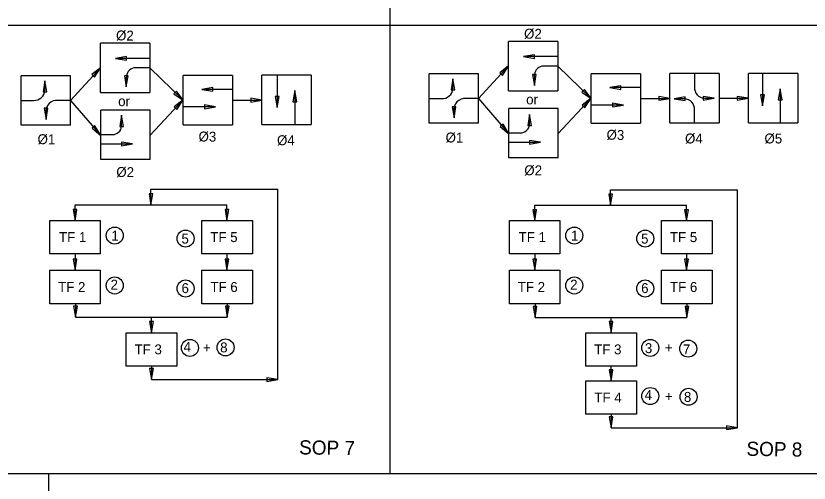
# Model space of a CAD drawing. Extents: x 10027 to 10796, y 10033 to 10528.
# Drawn here: x 10372.3 to 10652, y 10201.9 to 10366.7 of the extents above; entities that cross this region are included whole.
import ezdxf

# ---------------------------------------------------------------- set-up
doc = ezdxf.new("R2010")
doc.units = 0
for name, color, linetype in [('AdhocPoint_dp', 7, 'Continuous'), ('Default', 7, 'Continuous'), ('Dimension', 7, 'Continuous'), ('DSIndex', 7, 'Continuous'), ('PlotBorder_dp', 7, 'Continuous')]:
    doc.layers.add(name, color=color, linetype=linetype)

msp = doc.modelspace()

# ---------------------------------------------------------------- linework, layer by layer
at = {"layer": 'AdhocPoint_dp'}
for p, q in [((10504.32, 10205.22), (10504.32, 10528.43)), ((10027.5, 10363.43), (10662.13, 10363.43)), ((10662.13, 10205.22), (10027.5, 10205.22)), ((10383.78, 10205.22), (10383.78, 10033.43))]:
    msp.add_line(p, q, dxfattribs=at)
at = {"layer": 'Default'}
for p, q in [((10402.15, 10339.66), (10402.15, 10357.05)), ((10419.55, 10357.05), (10402.15, 10357.05)), ((10419.55, 10357.05), (10419.55, 10339.66)), ((10546.04, 10340.27), (10546.04, 10357.66)), ((10563.44, 10357.66), (10546.04, 10357.66)), ((10563.44, 10357.66), (10563.44, 10340.27)), ((10419.55, 10351.72), (10407.36, 10351.72)), ((10563.44, 10352.33), (10551.26, 10352.33)), ((10391.55, 10336.91), (10402.15, 10348.41)), ((10535.45, 10337.52), (10546.04, 10349.03)), ((10563.44, 10348.97), (10557.78, 10348.97)), ((10563.44, 10348.97), (10575.14, 10337.6)), ((10391.55, 10345.6), (10374.16, 10345.6)), ((10374.16, 10328.21), (10374.16, 10345.6)), ((10391.55, 10328.21), (10391.55, 10345.6)), ((10419.55, 10348.35), (10413.89, 10348.35)), ((10419.55, 10348.35), (10431.25, 10336.98)), ((10431.25, 10328.28), (10431.25, 10345.68)), ((10448.65, 10345.68), (10431.25, 10345.68)), ((10448.65, 10345.68), (10448.65, 10328.28)), ((10459.05, 10328.34), (10459.05, 10345.73)), ((10476.44, 10345.73), (10459.05, 10345.73)), ((10464.43, 10345.73), (10464.43, 10334.34)), ((10476.44, 10345.73), (10476.44, 10328.34)), ((10535.45, 10346.22), (10518.05, 10346.22)), ((10518.05, 10328.82), (10518.05, 10346.22)), ((10535.45, 10328.82), (10535.45, 10346.22)), ((10575.14, 10328.9), (10575.14, 10346.29)), ((10592.54, 10346.29), (10575.14, 10346.29)), ((10592.54, 10346.29), (10592.54, 10328.9)), ((10602.94, 10328.95), (10602.94, 10346.35)), ((10620.34, 10346.35), (10602.94, 10346.35)), ((10611.6, 10346.35), (10611.6, 10341.64)), ((10620.34, 10346.35), (10620.34, 10328.95)), ((10630.6, 10328.97), (10630.6, 10346.36)), ((10648, 10346.36), (10630.6, 10346.36)), ((10635.59, 10346.36), (10635.59, 10334.97)), ((10648, 10346.36), (10648, 10328.97)), ((10382.51, 10340.42), (10382.51, 10340.84)), ((10448.65, 10340.79), (10437.86, 10340.79)), ((10470.66, 10340.34), (10470.66, 10328.34)), ((10526.41, 10341.03), (10526.41, 10341.46)), ((10546.04, 10340.27), (10563.44, 10340.27)), ((10592.54, 10341.4), (10581.75, 10341.4)), ((10641.82, 10340.97), (10641.82, 10328.97)), ((10402.15, 10339.66), (10419.55, 10339.66)), ((10518.05, 10337.52), (10522.39, 10337.52)), ((10535.45, 10337.52), (10531.01, 10337.52)), ((10535.45, 10337.52), (10546.13, 10325.14)), ((10563.52, 10325.24), (10575.14, 10337.66)), ((10592.54, 10337.6), (10602.94, 10337.6)), ((10608.07, 10337.49), (10607.65, 10337.49)), ((10615.11, 10337.63), (10616.06, 10337.63)), ((10620.34, 10337.65), (10630.6, 10337.65)), ((10374.16, 10336.91), (10378.5, 10336.91)), ((10391.55, 10336.91), (10387.17, 10336.91)), ((10391.55, 10336.91), (10402.23, 10324.53)), ((10419.7, 10324.71), (10431.25, 10337.04)), ((10442.72, 10334.62), (10431.25, 10334.62)), ((10448.65, 10336.98), (10459.05, 10336.98)), ((10586.62, 10335.24), (10575.14, 10335.24)), ((10419.63, 10333.4), (10402.23, 10333.4)), ((10402.23, 10316.01), (10402.23, 10333.4)), ((10419.63, 10316.01), (10419.63, 10333.4)), ((10563.52, 10334.02), (10546.13, 10334.02)), ((10546.13, 10316.62), (10546.13, 10334.02)), ((10563.52, 10316.62), (10563.52, 10334.02)), ((10611.6, 10328.95), (10611.6, 10333.36)), ((10535.45, 10328.82), (10518.05, 10328.82)), ((10575.14, 10328.9), (10592.54, 10328.9)), ((10602.94, 10328.95), (10620.34, 10328.95)), ((10630.6, 10328.97), (10648, 10328.97)), ((10391.55, 10328.21), (10374.16, 10328.21)), ((10431.25, 10328.28), (10448.65, 10328.28)), ((10459.05, 10328.34), (10476.44, 10328.34)), ((10402.23, 10324.89), (10407.02, 10324.89)), ((10546.13, 10325.5), (10550.77, 10325.5)), ((10402.23, 10321.52), (10413.43, 10321.52)), ((10546.13, 10322.14), (10557.32, 10322.14)), ((10419.63, 10316.01), (10402.23, 10316.01)), ((10563.52, 10316.62), (10546.13, 10316.62)), ((10419.92, 10300.06), (10419.92, 10305.56)), ((10419.92, 10305.56), (10464.69, 10305.56)), ((10464.69, 10238.43), (10464.69, 10305.56)), ((10582.01, 10299.91), (10582.01, 10305.4)), ((10582.01, 10305.4), (10626.78, 10305.4)), ((10626.78, 10221.46), (10626.78, 10305.4)), ((10393.15, 10294.57), (10393.15, 10300.06)), ((10393.15, 10300.06), (10446.69, 10300.06)), ((10446.69, 10294.57), (10446.69, 10300.06)), ((10555.24, 10294.41), (10555.24, 10299.91)), ((10555.24, 10299.91), (10608.78, 10299.91)), ((10608.78, 10294.41), (10608.78, 10299.91)), ((10393.15, 10282.81), (10393.15, 10276.98)), ((10446.69, 10282.81), (10446.69, 10276.98)), ((10555.24, 10282.81), (10555.24, 10276.98)), ((10608.78, 10282.81), (10608.78, 10276.98)), ((10393.28, 10265.22), (10393.28, 10260.47)), ((10446.83, 10265.22), (10446.83, 10260.47)), ((10555.37, 10265.07), (10555.37, 10260.32)), ((10608.92, 10265.07), (10608.92, 10260.32)), ((10393.28, 10260.47), (10446.83, 10260.47)), ((10420.11, 10254.97), (10420.11, 10260.47)), ((10555.37, 10260.32), (10608.92, 10260.32)), ((10582.2, 10255.04), (10582.2, 10260.32)), ((10420.11, 10243.22), (10420.11, 10238.43)), ((10582.2, 10238.01), (10582.2, 10243.29)), ((10420.11, 10238.43), (10464.69, 10238.43)), ((10582.2, 10226.25), (10582.2, 10221.46)), ((10582.2, 10221.46), (10626.78, 10221.46))]:
    msp.add_line(p, q, dxfattribs=at)
for centre in [(10433.67, 10249.63), (10446.22, 10249.8)]:
    msp.add_circle(centre, 3, dxfattribs=at)
for centre, radius, start, end in [((10558.55, 10345.62), 3.44, 102.998, 182.423), ((10414.66, 10345), 3.44, 102.998, 182.423), ((10378.74, 10340.68), 3.78, 266.3242, 356.0955), ((10522.64, 10341.29), 3.78, 266.3242, 356.0955), ((10615.37, 10341.4), 3.78, 176.3242, 266.0955), ((10530.63, 10333.66), 3.88, 84.3849, 188.3023), ((10607.82, 10333.72), 3.78, 356.3242, 86.0955), ((10386.75, 10333.05), 3.88, 83.7387, 188.217), ((10550.31, 10328.63), 3.16, 278.4278, 6.6131), ((10406.42, 10328.02), 3.16, 278.4278, 6.6131)]:
    msp.add_arc(centre, radius, start, end, dxfattribs=at)
at = {"layer": 'Dimension'}
for p, q in [((10382.51, 10340.84), (10382.51, 10343.76)), ((10411.22, 10344.86), (10411.22, 10341.71)), ((10526.41, 10341.46), (10526.41, 10344.46)), ((10555.12, 10345.47), (10555.12, 10342.16)), ((10607.65, 10337.49), (10604.42, 10337.49)), ((10616.06, 10337.63), (10616.06, 10337.62)), ((10616.06, 10337.62), (10618.6, 10337.62)), ((10382.91, 10332.49), (10382.91, 10330.21)), ((10409.56, 10328.38), (10409.56, 10331.63)), ((10526.79, 10333.1), (10526.79, 10330.75)), ((10553.45, 10328.99), (10553.45, 10331.92))]:
    msp.add_line(p, q, dxfattribs=at)
for centre in [(10407.13, 10289.22), (10432.13, 10288.16), (10569.22, 10289.22), (10594.22, 10288.16), (10407.13, 10271.63), (10432.13, 10270.57), (10569.22, 10271.63), (10594.22, 10270.57), (10596.02, 10249.63), (10609.39, 10249.36), (10596.01, 10232.66), (10609.51, 10232.41)]:
    msp.add_circle(centre, 3, dxfattribs=at)
at = {"layer": 'DSIndex'}
for points in [[(10384.24, 10294.57), (10402.06, 10294.57), (10402.06, 10282.81), (10384.24, 10282.81)], [(10437.89, 10294.57), (10455.72, 10294.57), (10455.72, 10282.81), (10437.89, 10282.81)], [(10546.33, 10294.57), (10564.15, 10294.57), (10564.15, 10282.81), (10546.33, 10282.81)], [(10599.98, 10294.57), (10617.81, 10294.57), (10617.81, 10282.81), (10599.98, 10282.81)], [(10384.24, 10276.98), (10402.06, 10276.98), (10402.06, 10265.22), (10384.24, 10265.22)], [(10437.89, 10276.98), (10455.72, 10276.98), (10455.72, 10265.22), (10437.89, 10265.22)], [(10546.33, 10276.98), (10564.15, 10276.98), (10564.15, 10265.22), (10546.33, 10265.22)], [(10599.98, 10276.98), (10617.81, 10276.98), (10617.81, 10265.22), (10599.98, 10265.22)], [(10411.2, 10254.97), (10429.02, 10254.97), (10429.02, 10243.22), (10411.2, 10243.22)], [(10573.29, 10254.97), (10591.11, 10254.97), (10591.11, 10243.22), (10573.29, 10243.22)], [(10573.29, 10238.01), (10591.11, 10238.01), (10591.11, 10226.25), (10573.29, 10226.25)]]:
    msp.add_lwpolyline(points, close=True, dxfattribs=at)
at = {"layer": 'PlotBorder_dp'}
for points in [[(10407.36, 10351.72), (10411.27, 10351.06), (10411.27, 10352.38)], [(10551.26, 10352.33), (10555.16, 10351.67), (10555.16, 10352.99)], [(10402.15, 10348.41), (10399.02, 10345.99), (10399.99, 10345.09)], [(10546.04, 10349.03), (10542.91, 10346.6), (10543.89, 10345.71)], [(10411.22, 10341.71), (10411.88, 10345.61), (10410.56, 10345.61)], [(10555.12, 10342.16), (10555.78, 10346.07), (10554.45, 10346.07)], [(10382.51, 10343.76), (10381.85, 10339.86), (10383.17, 10339.86)], [(10526.41, 10344.46), (10525.74, 10340.56), (10527.07, 10340.56)], [(10431.25, 10336.98), (10428.91, 10340.18), (10427.99, 10339.23)], [(10437.86, 10340.79), (10441.76, 10340.13), (10441.76, 10341.45)], [(10470.66, 10340.34), (10470, 10336.44), (10471.32, 10336.44)], [(10575.14, 10337.6), (10572.8, 10340.79), (10571.88, 10339.84)], [(10581.75, 10341.4), (10585.66, 10340.74), (10585.66, 10342.07)], [(10641.82, 10340.97), (10641.16, 10337.07), (10642.48, 10337.07)], [(10459.05, 10336.98), (10455.14, 10337.64), (10455.14, 10336.32)], [(10464.43, 10334.34), (10465.09, 10338.24), (10463.76, 10338.24)], [(10575.14, 10337.66), (10571.99, 10335.26), (10572.96, 10334.35)], [(10602.94, 10337.6), (10599.04, 10338.26), (10599.04, 10336.93)], [(10604.42, 10337.49), (10608.33, 10336.83), (10608.33, 10338.15)], [(10618.6, 10337.62), (10614.69, 10338.28), (10614.69, 10336.96)], [(10630.6, 10337.65), (10626.7, 10338.31), (10626.7, 10336.99)], [(10635.59, 10334.97), (10636.25, 10338.87), (10634.93, 10338.87)], [(10431.25, 10337.04), (10428.1, 10334.64), (10429.06, 10333.74)], [(10442.72, 10334.62), (10438.82, 10335.29), (10438.82, 10333.96)], [(10526.79, 10330.75), (10527.45, 10334.65), (10526.13, 10334.65)], [(10586.62, 10335.24), (10582.71, 10335.9), (10582.71, 10334.58)], [(10382.91, 10330.21), (10383.57, 10334.12), (10382.25, 10334.12)], [(10409.56, 10331.63), (10408.9, 10327.73), (10410.22, 10327.73)], [(10553.45, 10331.92), (10552.79, 10328.01), (10554.11, 10328.01)], [(10402.23, 10324.53), (10400.18, 10327.91), (10399.18, 10327.05)], [(10546.13, 10325.14), (10544.08, 10328.53), (10543.08, 10327.67)], [(10413.43, 10321.52), (10409.52, 10322.18), (10409.52, 10320.86)], [(10557.32, 10322.14), (10553.41, 10322.8), (10553.41, 10321.48)], [(10419.92, 10300.06), (10420.58, 10303.97), (10419.26, 10303.97)], [(10582.01, 10299.91), (10582.67, 10303.81), (10581.35, 10303.81)], [(10393.15, 10294.57), (10393.81, 10298.47), (10392.49, 10298.47)], [(10446.69, 10294.57), (10447.35, 10298.47), (10446.03, 10298.47)], [(10555.24, 10294.41), (10555.9, 10298.32), (10554.58, 10298.32)], [(10608.78, 10294.41), (10609.45, 10298.32), (10608.12, 10298.32)], [(10393.15, 10276.98), (10393.81, 10280.88), (10392.49, 10280.88)], [(10446.69, 10276.98), (10447.35, 10280.88), (10446.03, 10280.88)], [(10555.24, 10276.98), (10555.9, 10280.88), (10554.58, 10280.88)], [(10608.78, 10276.98), (10609.45, 10280.88), (10608.12, 10280.88)], [(10393.28, 10260.47), (10393.95, 10264.38), (10392.62, 10264.38)], [(10446.83, 10260.47), (10447.49, 10264.38), (10446.17, 10264.38)], [(10555.37, 10260.32), (10556.04, 10264.22), (10554.71, 10264.22)], [(10608.92, 10260.32), (10609.58, 10264.22), (10608.26, 10264.22)], [(10420.11, 10254.97), (10420.77, 10258.88), (10419.45, 10258.88)], [(10582.2, 10255.04), (10582.86, 10258.95), (10581.54, 10258.95)], [(10420.11, 10238.43), (10420.77, 10242.34), (10419.45, 10242.34)], [(10582.2, 10238.01), (10582.86, 10241.91), (10581.54, 10241.91)], [(10464.69, 10238.43), (10460.79, 10239.09), (10460.79, 10237.77)], [(10582.2, 10221.46), (10582.86, 10225.37), (10581.54, 10225.37)], [(10582.2, 10221.46), (10582.86, 10225.37), (10581.54, 10225.37)], [(10626.78, 10221.46), (10622.88, 10222.13), (10622.88, 10220.8)]]:
    msp.add_lwpolyline(points, close=True, dxfattribs=at)

# ---------------------------------------------------------------- texts
at = {"layer": 'Default'}
for s, height, rotation, p in [('4', 3.5, 359.6943, (10431.42, 10248.26)), ('8', 3.5, 359.6943, (10444.31, 10248.06)), ('SOP 7', 5, 359.1183, (10472.14, 10212.09)), ('SOP 8', 5, 359.1183, (10629.91, 10211.59))]:
    msp.add_text(s, height=height, rotation=rotation, dxfattribs=at).set_placement(p)
msp.add_text('+', height=3.5, dxfattribs=at).set_placement((10438.29, 10248))
at = {"layer": 'Dimension'}
for s, rotation, p in [('Ø2', 359.1183, (10407.58, 10358.07)), ('Ø2', 359.1183, (10551.48, 10358.69)), ('or', 359.1183, (10408.32, 10334.9)), ('or', 359.1183, (10552.21, 10335.51)), ('Ø3', 359.1183, (10436.68, 10322.43)), ('Ø3', 359.1183, (10580.57, 10323.04)), ('Ø1', 359.1183, (10379.9, 10321.48)), ('Ø1', 359.1183, (10523.8, 10322.09)), ('Ø2', 359.1183, (10407.67, 10309.92)), ('Ø2', 359.1183, (10551.56, 10310.54)), ('1', 359.6943, (10405.97, 10287.47)), ('5', 359.6943, (10430.67, 10286.41)), ('1', 359.6943, (10568.06, 10287.47)), ('5', 359.6943, (10592.76, 10286.41)), ('2', 359.6943, (10405.65, 10270.19)), ('2', 359.6943, (10567.74, 10270.19)), ('6', 359.6943, (10430.69, 10268.96)), ('6', 359.6943, (10592.79, 10268.96)), ('3', 359.6943, (10594.1, 10247.79)), ('7', 359.6943, (10607.48, 10247.35)), ('4', 359.6943, (10593.98, 10231.24)), ('8', 359.6943, (10607.87, 10230.6))]:
    msp.add_text(s, height=3.5, rotation=rotation, dxfattribs=at).set_placement(p)
for s, p in [('Ø4', (10464.38, 10321.1)), ('Ø4', (10608.27, 10321.71)), ('Ø5', (10636.29, 10321.71)), ('TF 1', (10387.5, 10286.94)), ('TF 5', (10440.85, 10286.94)), ('TF 1', (10549.59, 10286.94)), ('TF 5', (10602.94, 10286.94)), ('TF 2', (10387.18, 10269.35)), ('TF 6', (10440.88, 10269.35)), ('TF 2', (10549.27, 10269.35)), ('TF 6', (10602.97, 10269.35)), ('TF 3', (10414.14, 10247.35)), ('TF 3', (10576.23, 10247.35)), ('+', (10601.14, 10247.98)), ('TF 4', (10576.3, 10230.38)), ('+', (10601.18, 10230.84))]:
    msp.add_text(s, height=3.5, dxfattribs=at).set_placement(p)

doc.saveas('drawing.dxf')
